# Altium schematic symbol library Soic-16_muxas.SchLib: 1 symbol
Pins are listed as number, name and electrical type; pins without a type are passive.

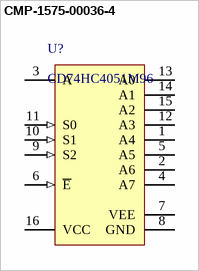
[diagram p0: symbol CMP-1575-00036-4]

## CMP-1575-00036-4
designator U?, comment CD74HC4051M96
High Speed CMOS 8-Channel Analog Multiplexer/Demultiplexer, D0016A, LARGE T&R; Manufacturer: Texas Instruments; Crosstalk: Yes; Ron(Max)(Ohms): 130; VCC(Min)(V): 2; Bandwidth(Max)(MHz): 180; VCC(Max)(V): 6; Rating: Catalog; Configuration: 1 X 1：8 MUX; Ron(Typ)(Ohms): 45
footprint D0016A_N (SOIC, 16-Leads, Body 10x4mm, Pitch 1.27mm, IPC Medium Density)
footprint D0016A_L (SOIC, 16-Leads, Body 10x4mm, Pitch 1.27mm, IPC High Density)
footprint D0016A_M (SOIC, 16-Leads, Body 10x4mm, Pitch 1.27mm, IPC Low Density)
pins: 1 A4, 2 A6, 3 A, 4 A7, 5 A5, 6 ~{E} (in), 7 VEE (power), 8 GND (power), 9 S2 (in), 10 S1 (in), 11 S0 (in), 12 A3, 13 A0, 14 A1, 15 A2, 16 VCC (power)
